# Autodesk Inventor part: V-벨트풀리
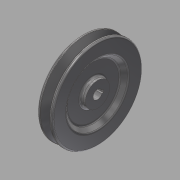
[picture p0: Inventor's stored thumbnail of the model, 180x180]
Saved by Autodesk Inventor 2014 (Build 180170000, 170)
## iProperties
Created: 2015-12
Part Number: V-벨트풀리
Document SubType Name: Modeling
Designer: mdu
Density: 8.08 g/cm^3
Material: 스테인리스강
Appearance: 반광택
Mass: 1135.51 g
Surface Area: 369.462 cm^2
Volume: 140.533 cm^3
Author: mdu
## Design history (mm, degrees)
sketch "스케치1"
  geometry: L1 (-10, 0)-(10, 0); L2 (-10, 0)-(-10, 16); L3 (-10, 16)-(-4, 16); L4 (-4, 16)-(-4, 35); L5 (-4, 35)-(-10, 41); L6 (-10, 41)-(-10, 59.5); L7 (-10, 59.5)-(-6.062, 59.5); L8 (-6.062, 59.5)-(-2.001, 47); L9 (-2.001, 47)-(2.001, 47); L10 (2.001, 47)-(6.062, 59.5); L11 (6.062, 59.5)-(10, 59.5); L12 (10, 59.5)-(10, 41); L13 (10, 41)-(4, 35); L14 (4, 35)-(4, 16); L15 (4, 16)-(10, 16); L16 (10, 16)-(10, 0); L17 (-4.6, 55)-(4.6, 55); 2 further points
  constraints: 34 end point, 7 parallel, 6 equal length, 5 collinear, 3 perpendicular, 2 point on line, 1 coincident, 1 horizontal, 1 midpoint
  dimensions: "d0" = 20 distance of L1.start L1.end; "d1" = 9.2 distance of L17.start L17.end; "d2" = 36 deg angle of L10 L8; "d3" = 4.5 distance between parallel lines of L7 L17; "d4" = 8 distance between parallel lines of L9 L17; "d6" = 110 diameter of L17 L1; "d7" = 32 diameter of L3 L1; "d8" = 82 diameter of L5.end L1; "d9" = 6 distance of L2.end L3.end; "d10" = 135 deg angle of L4 L5
revolve "회전1" sketch "스케치1" stored, may be unused: angle "d11" = 90 deg
fillet "모깎기1" dims "d12" = 2, "d13" = 0.5, "d14" = 1, "d15" = 3
sketch "스케치2"
  geometry: L1 (-2, 5.657)-(-2, 7.8); L2 (-2, 7.8)-(2, 7.8); L3 (2, 7.8)-(2, 5.657); A1 r 6 centre (0, 0) between (-2, 5.657) and (2, 5.657); 1 further point
  constraints: 6 end point, 2 parallel, 2 point on circle, 1 centre point, 1 coincident, 1 perpendicular, 1 vertical
  dimensions: "d16" = 12 diameter of A1; "d17" = 4 distance of L1.end L2.end; "d18" = 13.8 dimension on A1 L2 (computed from d16)
extrude "돌출1" cut sketch "스케치2" stored distance "d19" = 10; taper "d20" = 0 deg
node "솔리드1"
